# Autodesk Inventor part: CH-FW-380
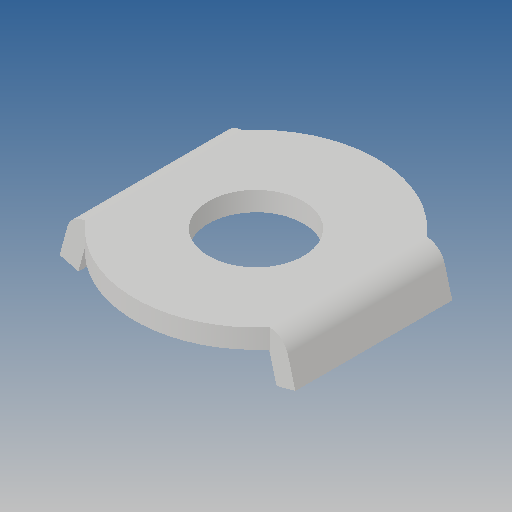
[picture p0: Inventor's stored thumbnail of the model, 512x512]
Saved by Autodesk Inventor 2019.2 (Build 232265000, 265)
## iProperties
Created: 2012-09
Part Number: CH-FW-380
Material: Ogólny
Document SubType Name: Modeling
Designer: CADENGINEERING4
Density: 1 g/cm^3
Appearance: Domyślna
Author: CADENGINEERING4
Revision Number: ÈÎºÎ
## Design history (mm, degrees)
feature "ÇÐ³ý-À­Éì1"
node "Bryła1"
